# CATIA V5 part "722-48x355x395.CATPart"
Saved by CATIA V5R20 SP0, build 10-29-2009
Part number: 722-48x355x395
Definition: NONE
Nomenclature: 722-48x355x395
Source: Unknown
Description: 722-48x355x395
Bounding box of the stored display mesh (mm): x -24 to 24, y -23.825 to 23.825, z -337 to 58
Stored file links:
  C:\Users\Utente\Desktop\IO LAVORO\3D X SITO CF\X SITO\722\722-48x355x395.CATPart
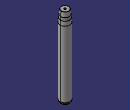
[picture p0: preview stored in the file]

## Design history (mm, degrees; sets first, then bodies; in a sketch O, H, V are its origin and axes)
Body1 "722-48x355x395" (main body)
  Solid1: solid without history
